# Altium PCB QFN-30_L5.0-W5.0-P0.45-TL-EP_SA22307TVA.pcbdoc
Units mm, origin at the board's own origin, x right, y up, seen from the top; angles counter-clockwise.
Board outline 18.99 x 18.42 mm, 2 copper layers (Top Layer, Bottom Layer), stack 0 mm thick; 1 components, 0 nets, 31 pads, 0 vias.
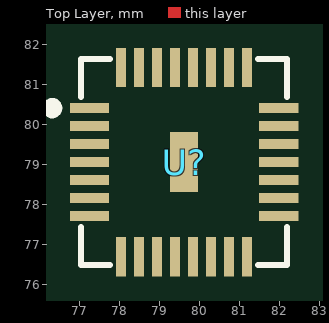
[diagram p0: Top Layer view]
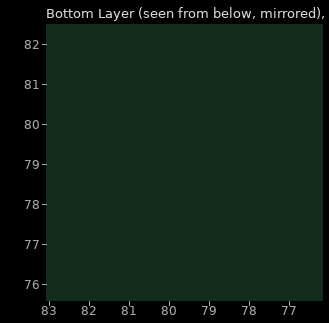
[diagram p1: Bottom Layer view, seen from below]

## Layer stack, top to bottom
Top Layer: signal copper (thickness not stored)
Bottom Layer: signal copper (thickness not stored)

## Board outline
88.837,69.85 69.85,69.85 69.85,88.27 88.837,88.27

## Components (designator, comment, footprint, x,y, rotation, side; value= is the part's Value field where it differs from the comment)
U? "" QFN-30_L5.0-W5.0-P0.45-TL-EP_SA22307TVA 79.627,79.06 r0 top

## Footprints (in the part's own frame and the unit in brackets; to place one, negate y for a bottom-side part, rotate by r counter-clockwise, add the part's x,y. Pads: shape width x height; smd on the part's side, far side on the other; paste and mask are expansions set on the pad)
QFN-30_L5.0-W5.0-P0.45-TL-EP_SA22307TVA [mm]
  rect 0.985x0.252 smd: 1(-2.368,1.35) 2(-2.368,0.9) 3(-2.368,0.45) 4(-2.368,0) 5(-2.368,-0.45) 6(-2.368,-0.9) 7(-2.368,-1.35) 16(2.368,-1.35) 17(2.368,-0.9) 18(2.368,-0.45) 19(2.368,0) 20(2.368,0.45) 21(2.368,0.9) 22(2.368,1.35)
  rect 0.252x0.985 smd: 8(-1.575,-2.368) 9(-1.125,-2.368) 10(-0.675,-2.368) 11(-0.225,-2.368) 12(0.225,-2.368) 13(0.675,-2.368) 14(1.125,-2.368) 15(1.575,-2.368) 23(1.575,2.368) 24(1.125,2.368) 25(0.675,2.368) 26(0.225,2.368) 27(-0.225,2.368) 28(-0.675,2.368) 29(-1.125,2.368) 30(-1.575,2.368)
  rect 0.7x1.5 smd: 31(0,0)
  silkscreen extent -3.43,-2.58 2.58,2.58

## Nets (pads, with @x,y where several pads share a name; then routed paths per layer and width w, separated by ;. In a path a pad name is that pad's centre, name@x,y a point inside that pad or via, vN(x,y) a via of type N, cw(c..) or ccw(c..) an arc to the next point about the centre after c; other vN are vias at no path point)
pads on no net: U?.1 U?.2 U?.3 U?.4 U?.5 U?.6 U?.7 U?.8 U?.9 U?.10 U?.11 U?.12 U?.13 U?.14 U?.15 U?.16 U?.17 U?.18 U?.19 U?.20 U?.21 U?.22 U?.23 U?.24 U?.25 U?.26 U?.27 U?.28 U?.29 U?.30 U?.31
